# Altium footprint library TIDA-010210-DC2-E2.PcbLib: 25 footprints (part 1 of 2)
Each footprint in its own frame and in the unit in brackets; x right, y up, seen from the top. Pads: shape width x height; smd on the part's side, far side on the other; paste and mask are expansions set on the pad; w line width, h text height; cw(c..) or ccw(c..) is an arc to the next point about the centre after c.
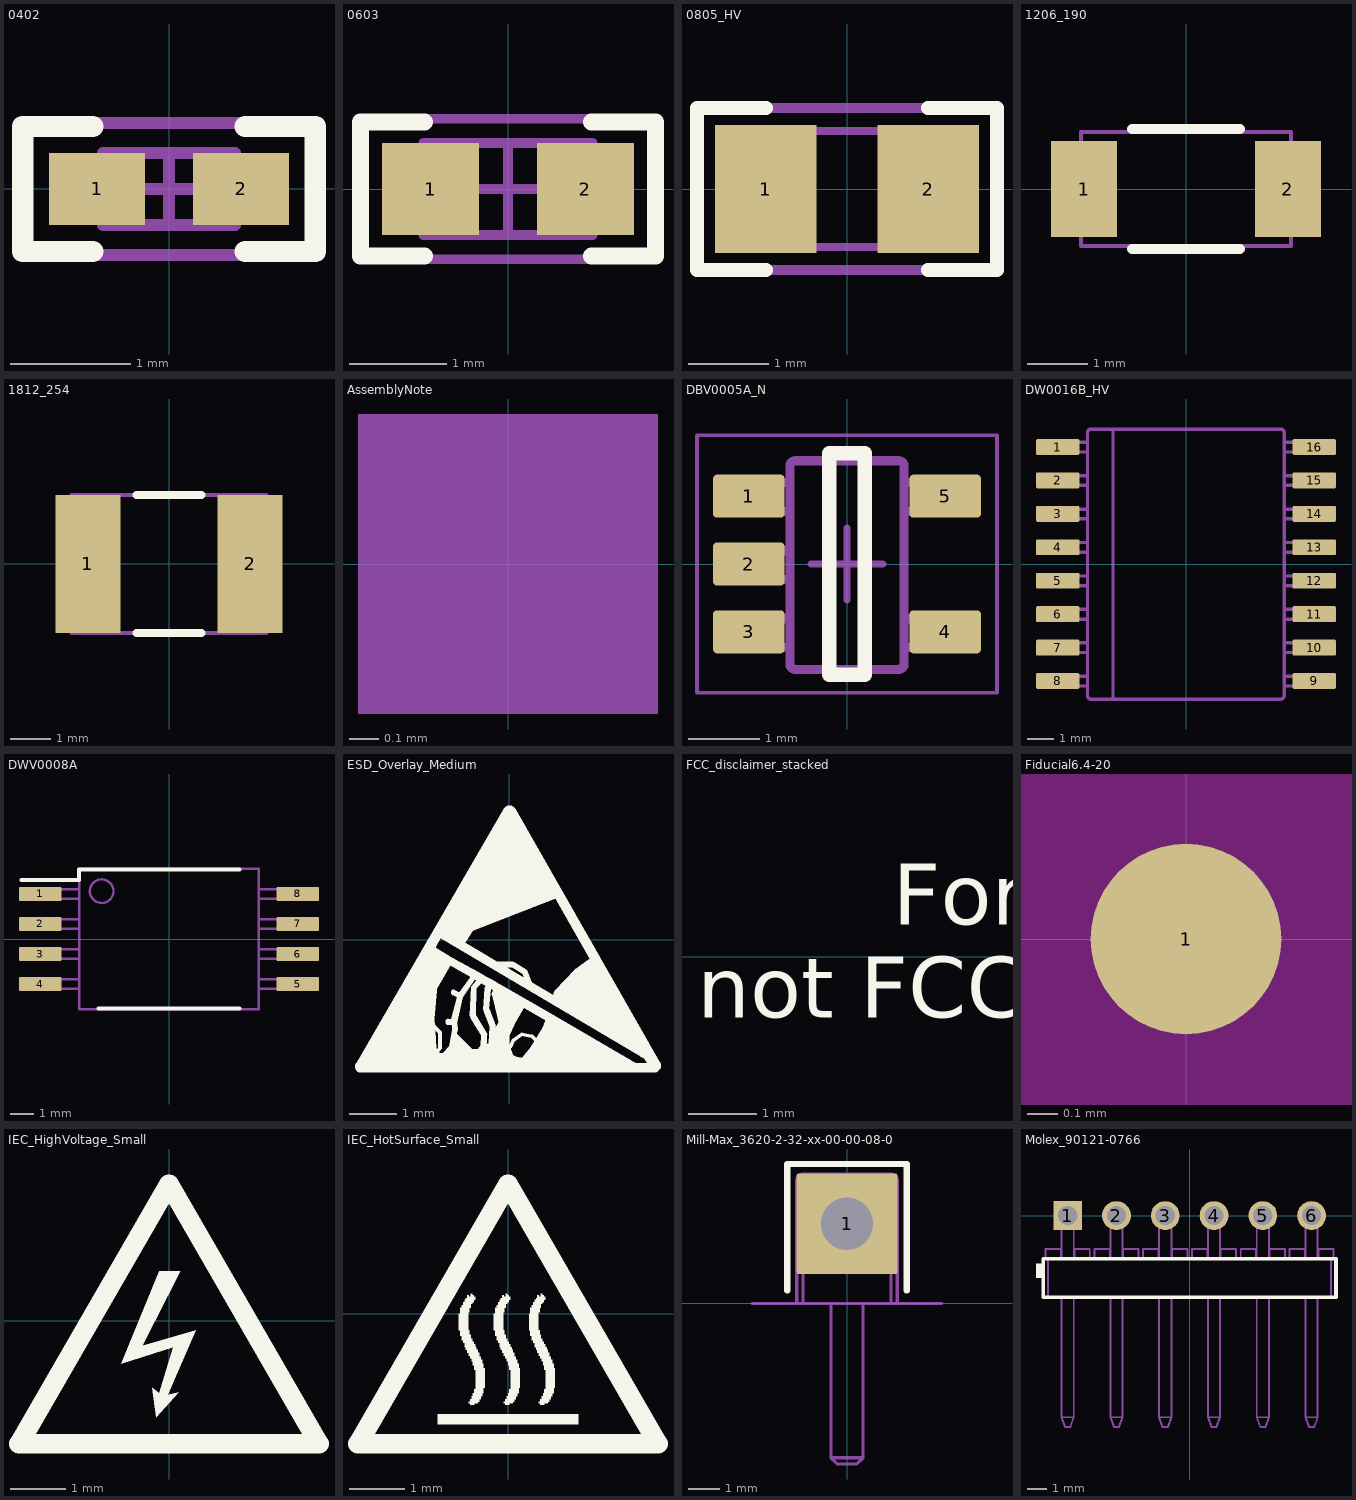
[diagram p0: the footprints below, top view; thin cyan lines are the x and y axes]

## 0402 [mm] "0402 from SM-752 data"
height 0.6
pads (2):
  rect 0.8x0.6 smd: 1(-0.6,0) 2(0.6,0)
Top Overlay:
  lines w0.178: -0.635,-0.521 -1.219,-0.521 -1.219,0.521 -0.635,0.521 ; 0.635,-0.521 1.219,-0.521 1.219,0.521 0.635,0.521
Mechanical 5:
  lines w0.1: -1.25,-0.55 -1.25,0.55 1.25,0.55 1.25,-0.55 -1.25,-0.55
  text ".Designator" at -1.117,-0.305 h0.61
Mechanical 13:
  lines w0.1: -0.35,-0.3 -0.35,0.3 ; 0.35,-0.3 0.35,0.3 ; -0.55,-0.3 0.55,-0.3 0.55,0.3 -0.55,0.3 -0.55,-0.3
Mechanical 15:
  lines w0.1: -0.3,0 0.3,0 ; 0,-0.3 0,0.3 ; -1.25,-0.55 1.25,-0.55 1.25,0.55 -1.25,0.55 -1.25,-0.55
3D body: height 0.6, standoff 0, extent 0.351,-0.299 0.549,0.299
3D body: height 0.6, standoff 0, extent -0.349,-0.299 0.349,0.299
3D body: height 0.6, standoff 0, extent -0.549,-0.299 -0.351,0.299

## 0603 [mm] "0603 from SM-752 data"
height 1
pads (2):
  rect 1x0.95 smd: 1(-0.8,0) 2(0.8,0)
Top Overlay:
  lines w0.178: -0.864,-0.691 -1.524,-0.691 -1.524,0.693 -0.864,0.693 ; 0.864,-0.691 1.524,-0.691 1.524,0.693 0.864,0.693
Mechanical 5:
  lines w0.1: -1.55,-0.725 -1.55,0.725 1.55,0.725 1.55,-0.725 -1.55,-0.725
  text ".Designator" at -0.61,-0.236 h0.46
Mechanical 13:
  lines w0.1: -0.55,-0.475 -0.55,0.475 ; 0.55,-0.475 0.55,0.475 ; -0.875,-0.475 0.875,-0.475 0.875,0.475 -0.875,0.475 -0.875,-0.475
Mechanical 15:
  lines w0.1: -0.475,0 0.475,0 ; 0,-0.475 0,0.475 ; -1.55,-0.725 1.55,-0.725 1.55,0.725 -1.55,0.725 -1.55,-0.725
3D body: height 1, standoff 0, extent -0.874,-0.474 -0.551,0.474
3D body: height 1, standoff 0, extent -0.549,-0.474 0.549,0.474
3D body: height 1, standoff 0, extent 0.551,-0.474 0.874,0.474

## 0805_HV [mil] "0805 with 30mil clearance between pads"
height 57.09
pads (2):
  rect 50x63 smd: 1(-40,0) 2(40,0)
Top Overlay:
  lines w7: -40,-40 -74,-40 -74,0 -74,40 -40,40 ; 40,-40 74,-40 74,0 74,40 40,40
Mechanical 5:
  lines w5: -74,-40 -74,40 74,40 74,-40 -74,-40
  text ".Designator" at -64,-17 h35
Mechanical 13:
  lines w3.94: -25.59,-28.54 -25.59,28.54 ; 25.59,-28.54 25.59,28.54 ; -43.31,-28.54 -43.31,28.54 43.31,28.54 43.31,-28.54 -43.31,-28.54
3D body: height 57.09, standoff 0, extent 25.61,-28.52 43.29,28.52
3D body: height 57.09, standoff 0, extent -25.57,-28.52 25.57,28.52
3D body: height 57.09, standoff 0, extent -43.29,-28.52 -25.61,28.52

## 1206_190 [mm] "1206_190"
height 1.9
pads (2):
  rect 1.1x1.6 smd: 1(-1.7,0) 2(1.7,0)
Top Overlay:
  lines w0.17: -0.9,-1 0.9,-1 ; -0.9,1 0.9,1
Mechanical 5:
  lines w0.07: -1.75,-0.95 1.75,-0.95 1.75,0.95 -1.75,0.95 -1.75,-0.95
  text ".Designator" at -1.5,-0.4 h0.81
3D body: height 1.9, standoff 0, extent -1.749,-0.949 -1.301,0.949
3D body: height 1.9, standoff 0, extent -1.299,-0.949 1.299,0.949
3D body: height 1.9, standoff 0, extent 1.301,-0.949 1.749,0.949

## 1812_254 [mm] "SMD, 2-Leads, Body 4.8x3.4mm"
height 2.54
pads (2):
  rect 1.6x3.4 smd: 1(-2,0) 2(2,0)
Top Overlay:
  lines w0.2: -0.8,-1.7 0.8,-1.7 ; -0.8,1.7 0.8,1.7
Mechanical 5:
  lines w0.1: -1.9,-1.7 -1.9,1.7 ; 1.9,-1.7 1.9,1.7 ; -2.4,-1.7 -2.4,1.7 2.4,1.7 2.4,-1.7 -2.4,-1.7
  text ".Designator" at -1.875,-0.5 h1.02
3D body: height 2.54, standoff 0, extent 1.901,-1.699 2.399,1.699
3D body: height 2.54, standoff 0, extent -1.899,-1.699 1.899,1.699
3D body: height 2.54, standoff 0, extent -2.399,-1.699 -1.901,1.699

## AssemblyNote [mm] "Assembly Note"
Mechanical 5:
  rectangle: -0.508,-0.508 0.508,0.508
  text ".Designator" at -4.191,-0.508 h0.46
  text ".Comment" at 1.143,-0.508 h0.46

## DBV0005A_N [mm] "SOT23, 5-Leads, Body 2.9x1.6mm, Pitch 0.95mm, Lead Span 2.8mm, IPC Medium Density"
height 1.45
pads (5):
  rrect17% 1x0.6 smd: 1(-1.375,0.95) 2(-1.375,0) 3(-1.375,-0.95) 4(1.375,-0.95) 5(1.375,0.95)
Top Overlay:
  lines w0.2: -0.25,-1.55 0.25,-1.55 0.25,1.55 -0.25,1.55 -0.25,-1.55
Mechanical 5:
  lines w0.127: -0.801,1.371 cw(c-0.725,1.37) -0.725,1.446 ; -0.801,1.37 -0.801,-1.399 -0.801,-1.4 ccw(c-0.725,-1.399) -0.725,-1.475 ; -0.801,1.37 -0.801,1.371 ; -0.725,-1.475 -0.725,-1.475 ; -0.725,-1.475 0.723,-1.475 0.724,-1.475 ccw(c0.723,-1.399) 0.799,-1.4 0.799,-1.399 0.799,1.37 ; -0.725,1.446 0.723,1.446 0.724,1.446 cw(c0.723,1.37) 0.799,1.371 ; -0.725,1.446 -0.725,1.446 ; 0.799,1.37 0.799,1.371 ; -1.423,-1.167 -1.199,-1.167 -1.105,-1.167 -1.088,-1.167 -0.835,-1.167 -0.801,-1.167 -0.801,-0.767 -0.835,-0.767 -1.088,-0.767 -1.105,-0.767 -1.199,-0.767 -1.423,-0.767 -1.423,-1.167 ; -1.423,-0.215 -1.199,-0.215 -1.105,-0.215 -1.088,-0.215 -0.835,-0.215 -0.801,-0.215 -0.801,0.186 -0.835,0.186 -1.088,0.186 -1.105,0.186 -1.199,0.186 -1.423,0.186 -1.423,-0.215 ; -1.423,0.738 -1.199,0.738 -1.105,0.738 -1.088,0.738 -0.835,0.738 -0.801,0.738 -0.801,1.138 -0.835,1.138 -1.088,1.138 -1.105,1.138 -1.199,1.138 -1.423,1.138 -1.423,0.738 ; 0.799,-1.167 0.799,-0.767 0.834,-0.767 1.087,-0.767 1.103,-0.767 1.198,-0.767 1.422,-0.767 1.422,-1.167 1.198,-1.167 1.103,-1.167 1.087,-1.167 0.834,-1.167 0.799,-1.167 ; 0.799,0.738 0.799,1.138 0.834,1.138 1.087,1.138 1.103,1.138 1.198,1.138 1.422,1.138 1.422,0.738 1.198,0.738 1.103,0.738 1.087,0.738 0.834,0.738 0.799,0.738
  text ".Designator" at -0.25,0.95 h0.51
Mechanical 15:
  lines w0.05: -2.1,-1.8 2.1,-1.8 2.1,1.8 -2.1,1.8 -2.1,-1.8
  lines w0.1: -0.5,0 0.5,0 ; 0,-0.5 0,0.5
3D body "DBV0005A.stp": height 1.09, standoff 0, extent -1.422,-1.461 1.423,1.46

## DW0016B_HV [mm] "SOIC-16, HV/isolation option"
height 2.65
pads (16):
  rrect17% 1.65x0.6 smd: 1(-4.875,4.445) 2(-4.875,3.175) 3(-4.875,1.905) 4(-4.875,0.635) 5(-4.875,-0.635) 6(-4.875,-1.905) 7(-4.875,-3.175) 8(-4.875,-4.445) 9(4.875,-4.445) 10(4.875,-3.175) 11(4.875,-1.905) 12(4.875,-0.635) 13(4.875,0.635) 14(4.875,1.905) 15(4.875,3.175) 16(4.875,4.445)
Mechanical 5:
  lines w0.1: -2.775,-5.135 -2.775,5.127
  lines w0.127: -3.74,-4.633 -5.15,-4.633 -5.15,-4.265 -3.74,-4.265 ; -3.74,-3.363 -5.15,-3.363 -5.15,-2.995 -3.74,-2.995 ; -3.74,-2.093 -5.15,-2.093 -5.15,-1.725 -3.74,-1.725 ; -3.74,-0.823 -5.15,-0.823 -5.15,-0.455 -3.74,-0.455 ; -3.74,0.447 -5.15,0.447 -5.15,0.815 -3.74,0.815 ; -3.74,1.717 -5.15,1.717 -5.15,2.085 -3.74,2.085 ; -3.74,2.987 -5.15,2.987 -5.15,3.355 -3.74,3.355 ; -3.74,4.257 -5.15,4.257 -5.15,4.625 -3.74,4.625 ; 3.74,-4.633 5.15,-4.633 5.15,-4.265 3.74,-4.265 ; 3.74,-3.363 5.15,-3.363 5.15,-2.995 3.74,-2.995 ; 3.74,-2.093 5.15,-2.093 5.15,-1.725 3.74,-1.725 ; 3.74,-0.823 5.15,-0.823 5.15,-0.455 3.74,-0.455 ; 3.74,0.447 5.15,0.447 5.15,0.815 3.74,0.815 ; 3.74,1.717 5.15,1.717 5.15,2.085 3.74,2.085 ; 3.74,2.987 5.15,2.987 5.15,3.355 3.74,3.355 ; 3.74,4.257 5.15,4.257 5.15,4.625 3.74,4.625 ; -3.74,-5.008 ccw(c-3.613,-5.008) -3.614,-5.135 3.601,-5.135 ccw(c3.6,-5.008) 3.727,-5.008 3.727,5 ccw(c3.6,5) 3.601,5.127 -3.614,5.127 ccw(c-3.613,5) -3.74,5 -3.74,-5.008
  text ".Designator" at -0.006,0.402 h0.46
3D body "DW0016B.stp": height 2.59, standoff 0, extent -5.167,-5.15 5.168,5.15

## DWV0008A [mm] "SOIC, 8-Leads, Body 5.95x7.6mm (max), Pitch 1.27mm"
height 2.8
pads (8):
  rrect17% 1.8x0.6 smd: 1(-5.45,1.905) 2(-5.45,0.635) 3(-5.45,-0.635) 4(-5.45,-1.905) 5(5.45,-1.905) 6(5.45,-0.635) 7(5.45,0.635) 8(5.45,1.905)
Top Overlay:
  lines w0.17: -6.25,2.5 -3.8,2.5 -3.8,2.95 2.975,2.95 ; -2.975,-2.95 2.975,-2.95
Mechanical 5:
  circle w0.1: c-2.85,2.025 r0.5
  lines w0.1: -3.805,-2.105 -5.8,-2.105 -5.8,-1.705 -3.805,-1.705 ; -3.805,-0.835 -5.8,-0.835 -5.8,-0.435 -3.805,-0.435 ; -3.805,0.435 -5.8,0.435 -5.8,0.835 -3.805,0.835 ; -3.805,1.705 -5.8,1.705 -5.8,2.105 -3.805,2.105 ; 3.805,-2.105 5.8,-2.105 5.8,-1.705 3.805,-1.705 ; 3.805,-0.835 5.8,-0.835 5.8,-0.435 3.805,-0.435 ; 3.805,0.435 5.8,0.435 5.8,0.835 3.805,0.835 ; 3.805,1.705 5.8,1.705 5.8,2.105 3.805,2.105 ; -3.8,-2.975 -3.8,2.975 3.8,2.975 3.8,-2.975 -3.8,-2.975
  text ".Designator" at -0.488,-0.195 h0.46
3D body "DWV0008A.stp": height 2.67, standoff -0.03, extent -5.768,-2.925 5.768,2.925

## ESD_Overlay_Medium [mm]
height 27
Top Overlay:
  drawing of 6916 lines, arcs and shapes, not listed

## FCC_disclaimer_stacked [mm]
height 7.62
Top Overlay:
  text "For evaluation only;" at -5.834,0.178 h1.52
  text "not FCC approved for resale." at -8.688,-1.178 h1.52

## Fiducial6.4-20 [mm]
height 19.05
pads (1):
  round 0.635 smd mask+0.683: 1(0,0)
Top Layer keep-out:
  circle w1.178: c0,0 r0.5

## IEC_HighVoltage_Small [mm]
Top Overlay:
  region: -0.178,0.889 0.203,0.889 -0.483,-0.457 0.483,-0.178 -0.025,-1.346 0.178,-1.295 -0.229,-1.753 -0.305,-1.219 -0.178,-1.321 0.076,-0.483 -0.864,-0.787
  lines w0.356: -2.718,-2.235 2.718,-2.235 0,2.472 -2.718,-2.235

## IEC_HotSurface_Small [mm]
height 19.05
Top Overlay:
  drawing of 10 lines, arcs and shapes, not listed

## Mill-Max_3620-2-32-xx-00-00-08-0 [mm] "PCB Pin, 0.04\" DIA, R/A, Edge-Mount"
height 0.635
pads (1):
  rrect3% 3.18x3.18 hole 1.65: 1(0,2.52)
Top Overlay:
  lines w0.2: -1.89,0.41 -1.89,4.41 1.89,4.41 1.89,0.41
Mechanical 1:
  lines w0.1: -3,0 3,0
Mechanical 5:
  lines w0.1: -0.51,0 -0.51,-4.88 ; 0.51,0 0.51,-4.88 ; -1.59,3.89 cw(c-1.39,3.89) -1.39,4.09 ; -1.59,3.89 -1.39,3.89 ; -1.59,3.89 -1.59,0 -1.39,0 ; -1.39,0 1.39,0 ; -1.39,0 -1.39,3.89 ; -1.39,3.89 -1.39,4.09 ; -1.39,3.89 1.39,3.89 ; -1.39,4.09 1.39,4.09 ; -0.51,-4.88 -0.31,-5.08 0.31,-5.08 0.51,-4.88 ; -0.51,-4.88 0.51,-4.88 ; 1.39,0 1.39,3.89 ; 1.39,0 1.59,0 1.59,3.89 ; 1.39,3.89 1.59,3.89 ; 1.39,3.89 1.39,4.09 ; 1.39,4.09 cw(c1.39,3.89) 1.59,3.89
  text ".Designator" at -0.714,1.676 h0.46
3D body "3620-2-32-xx-00-00-08-0.stp": height 0.65, standoff -2.53, extent -1.59,-5.06 1.59,4.11

## Molex_90121-0766 [mm] "Header, 2.54mm, 6x1, R/A, TH"
height 3.6
pads (6):
  rect 1.5x1.5 hole 1: 1(-6.35,0)
  round 1.5 hole 1: 2(-3.81,0) 3(-1.27,0) 4(1.27,0) 5(3.81,0) 6(6.35,0)
Top Overlay:
  rectangle: -8,-3.25 -7.62,-2.5
  lines w0.2: -7.62,-4.25 -7.37,-4.25 -5.469,-4.25 -5.175,-4.25 -4.985,-4.25 -4.691,-4.25 -2.929,-4.25 -2.635,-4.25 -2.445,-4.25 -2.151,-4.25 -0.389,-4.25 -0.095,-4.25 0.095,-4.25 0.389,-4.25 2.151,-4.25 2.445,-4.25 2.635,-4.25 2.929,-4.25 4.691,-4.25 4.985,-4.25 5.175,-4.25 5.469,-4.25 7.37,-4.25 7.62,-4.25 7.62,-2.25 -7.62,-2.25 -7.62,-4.25
Mechanical 5:
  drawing of 200 lines, arcs and shapes, not listed
  text ".Designator" at -0.008,-3.607 h0.46
3D body "901210766.stp": height 3.63, standoff -2.87, extent -7.62,-11 7.62,0.318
